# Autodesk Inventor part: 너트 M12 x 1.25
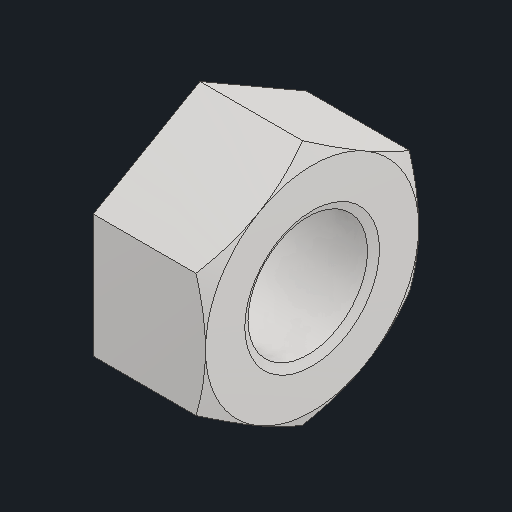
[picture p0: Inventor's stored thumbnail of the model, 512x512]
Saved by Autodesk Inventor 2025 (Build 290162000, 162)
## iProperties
Created: 2025-08
Part Number: 너트 M12 x 1.25
Material: 스테인리스강
Description: 6각 너트
Document SubType Name: Modeling
Designer: infra17
Density: 8.08 g/cm^3
Appearance: 기본값
Author: jhkim
Sending System: Autodesk Inventor 2026
Preprocessor: ST-DEVELOPER v20.1
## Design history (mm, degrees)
feature "Solid1"
node "솔리드1"
